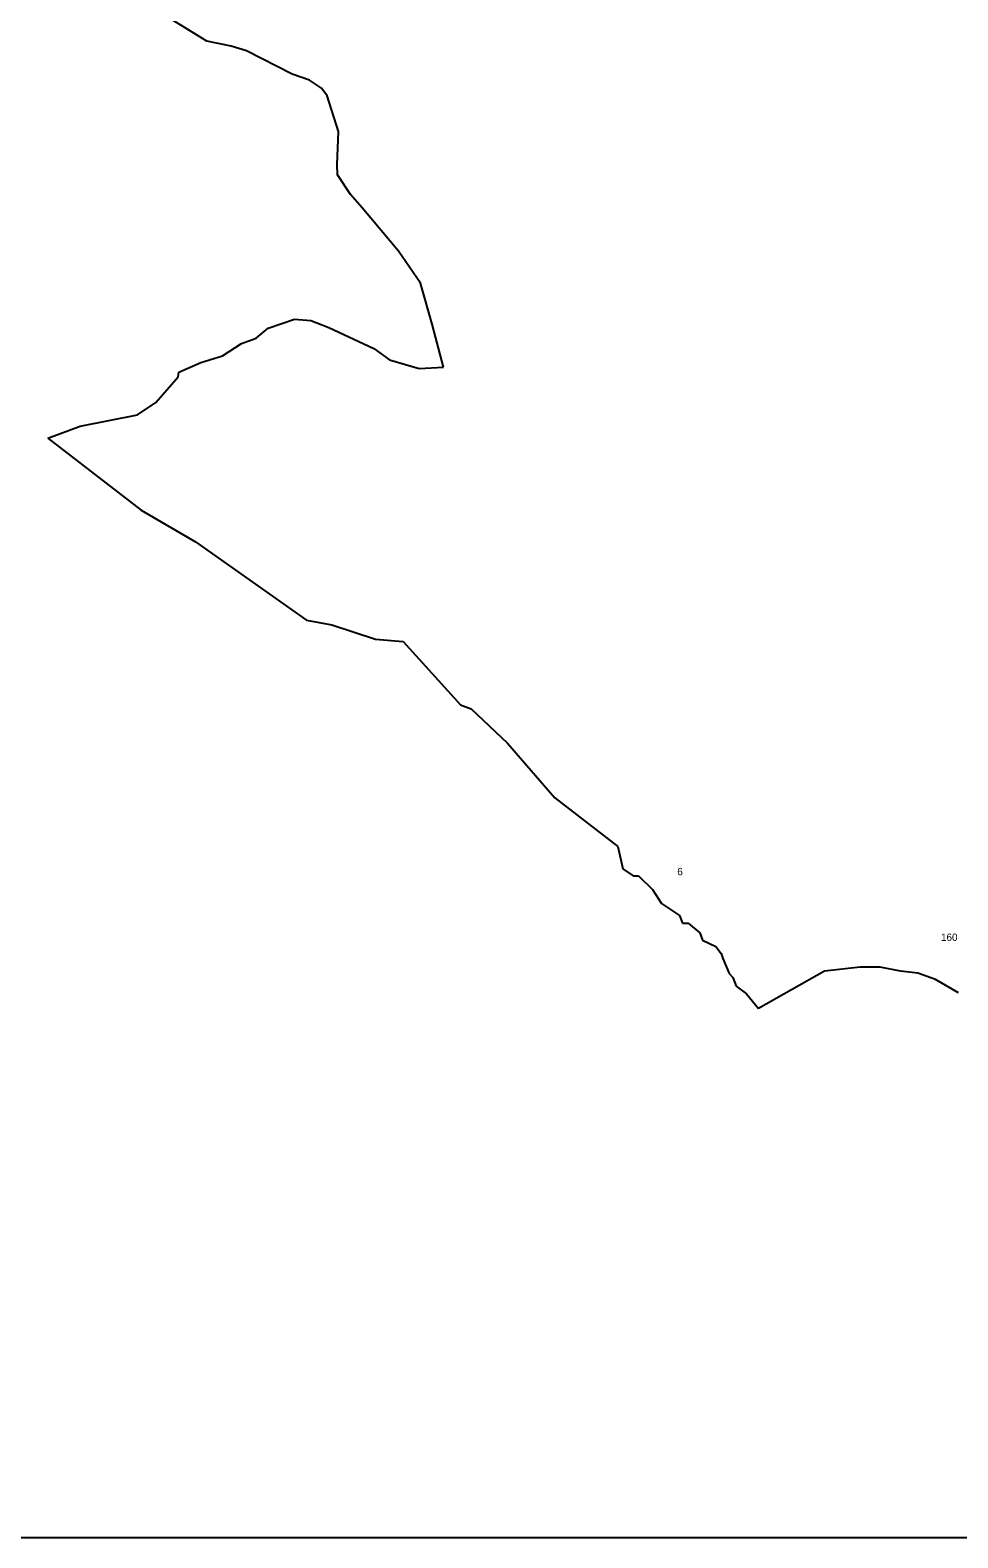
# Model space of a CAD drawing. Extents: x -787023 to -783617, y -975280 to -971607.
# Drawn here: x -785866 to -784731, y -975280 to -973436 of the extents above; entities that cross this region are included whole.
import ezdxf

# ---------------------------------------------------------------- set-up
doc = ezdxf.new("R2010")
doc.units = 0
for name, color, linetype in [('Vrstva 13', 7, 'Continuous'), ('Vrstva 15', 7, 'Continuous'), ('Vrstva 24', 7, 'Continuous')]:
    doc.layers.add(name, color=color, linetype=linetype)

msp = doc.modelspace()

# ---------------------------------------------------------------- linework, layer by layer
at = {"layer": 'Vrstva 13'}
for p, q in [((-785649.5, -973449.8), (-785707.9, -973413.8)), ((-785619.7, -973455.8), (-785649.5, -973449.8)), ((-785601, -973461.5), (-785619.7, -973455.8)), ((-785544.9, -973489.8), (-785601, -973461.5)), ((-785523.9, -973497.3), (-785544.9, -973489.8)), ((-785509.1, -973507.2), (-785523.9, -973497.3)), ((-785502.4, -973516.6), (-785509.1, -973507.2)), ((-785488.4, -973560.2), (-785502.4, -973516.6)), ((-785490, -973600.6), (-785488.4, -973560.2)), ((-785489.7, -973613.1), (-785490, -973600.6)), ((-785473.6, -973637.2), (-785489.7, -973613.1)), ((-785459.6, -973653.3), (-785473.6, -973637.2)), ((-785415.2, -973706.5), (-785459.6, -973653.3)), ((-785388, -973745.7), (-785415.2, -973706.5)), ((-785374, -973795.8), (-785388, -973745.7)), ((-785574.5, -973800.5), (-785542.1, -973789.6)), ((-785542.1, -973789.6), (-785522.1, -973791.1)), ((-785522.1, -973791.1), (-785500.3, -973800)), ((-785360, -973848.5), (-785374, -973795.8)), ((-785607.2, -973819.4), (-785589, -973812.9)), ((-785589, -973812.9), (-785574.5, -973800.5)), ((-785500.3, -973800), (-785445.1, -973825.4)), ((-785656.7, -973842.5), (-785630.3, -973834.5)), ((-785630.3, -973834.5), (-785607.2, -973819.4)), ((-785445.1, -973825.4), (-785426.1, -973839.4)), ((-785684.5, -973860.4), (-785683.5, -973854.7)), ((-785683.5, -973854.7), (-785656.7, -973842.5)), ((-785426.1, -973839.4), (-785389.6, -973850)), ((-785389.6, -973850), (-785360, -973848.5)), ((-785712, -973891.8), (-785684.5, -973860.4)), ((-785734.3, -973906.6), (-785712, -973891.8)), ((-785804.3, -973920.6), (-785734.3, -973906.6)), ((-785843.7, -973935.2), (-785804.3, -973920.6)), ((-785843.7, -973935.2), (-785729.6, -974023.2)), ((-785729.6, -974023.2), (-785663.4, -974062)), ((-785663.4, -974062), (-785527.7, -974157.7)), ((-785527.7, -974157.7), (-785496.5, -974163.6)), ((-785496.5, -974163.6), (-785443.2, -974181.1)), ((-785443.2, -974181.1), (-785409.5, -974184)), ((-785409.5, -974184), (-785339.1, -974261.4)), ((-785339.1, -974261.4), (-785326.2, -974266.4)), ((-785326.2, -974266.4), (-785281.7, -974308.5)), ((-785281.7, -974308.5), (-785223.8, -974375.1)), ((-785223.8, -974375.1), (-785146.8, -974434.7)), ((-785146.8, -974434.7), (-785140.6, -974462.1)), ((-785140.6, -974462.1), (-785128.1, -974470.5)), ((-785128.1, -974470.5), (-785121.4, -974470.5)), ((-785121.4, -974470.5), (-785104.4, -974487.5)), ((-785104.4, -974487.5), (-785093.5, -974504.6)), ((-785093.5, -974504.6), (-785071.4, -974519)), ((-785071.4, -974519), (-785067.6, -974528.6)), ((-785067.6, -974528.6), (-785060.6, -974528.6)), ((-785060.6, -974528.6), (-785046.6, -974540.2)), ((-785046.6, -974540.2), (-785043.1, -974549.4)), ((-785043.1, -974549.4), (-785027, -974557.1)), ((-785027, -974557.1), (-785020.5, -974565.5)), ((-785020.5, -974565.5), (-785018.2, -974571.7)), ((-785018.2, -974571.7), (-785010.5, -974590.2)), ((-785010.5, -974590.2), (-785006.2, -974594.9)), ((-785006.2, -974594.9), (-785002.2, -974605.7)), ((-785002.2, -974605.7), (-784989.6, -974614.8)), ((-784989.6, -974614.8), (-784974.9, -974632.7))]:
    msp.add_line(p, q, dxfattribs=at)
at = {"layer": 'Vrstva 15'}
for p, q in [((-784894, -974587.1), (-784974.9, -974632.7)), ((-784850.6, -974582.1), (-784894, -974587.1)), ((-784826.1, -974582.3), (-784850.6, -974582.1)), ((-784801.1, -974587.3), (-784826.1, -974582.3)), ((-784779.9, -974589.8), (-784801.1, -974587.3)), ((-784758.3, -974597.4), (-784779.9, -974589.8)), ((-784730.1, -974613.8), (-784758.3, -974597.4))]:
    msp.add_line(p, q, dxfattribs=at)
msp.add_lwpolyline([(-787022.7, -971607), (-783616.7, -971607), (-783616.7, -975280.4), (-787022.7, -975280.4)], close=True, dxfattribs=at)

# ---------------------------------------------------------------- texts
at = {"layer": 'Vrstva 24'}
for s, p in [('6', (-785074.1, -974469.9)), ('160', (-784751.5, -974550.2))]:
    msp.add_text(s, height=9, dxfattribs=at).set_placement(p)

doc.saveas('drawing.dxf')
